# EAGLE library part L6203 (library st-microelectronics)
DMOS FULL BRIDGE DRIVER
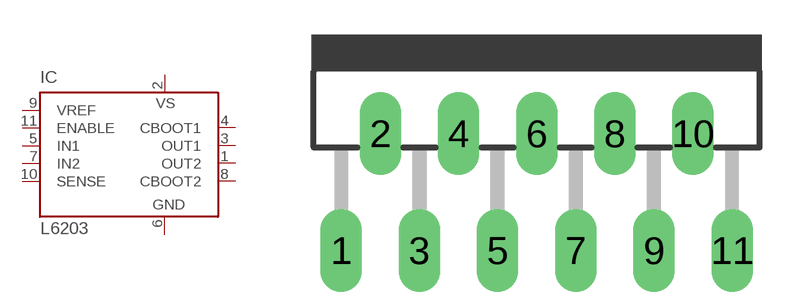
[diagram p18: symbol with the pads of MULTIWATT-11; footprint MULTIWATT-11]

Designator prefix IC

## L6203 (MPN: L6203; OC_FARNELL: 1467715; OC_NEWARK: 56P8434)  [MULTIWATT-11]
1  OUT2  out
2  VS  pwr
3  OUT1  out
4  CBOOT1  in
5  IN1  in
6  GND  pwr
7  IN2  in
8  CBOOT2  in
9  VREF  in
10  SENSE  in
11  ENABLE  in

## Footprint MULTIWATT-11 (pad centres in mm)
Muliwatt 11 lead
drill 1.2 long: 1 -8.5,-6.35; 2 -6.8,-1.27; 3 -5.1,-6.35; 4 -3.4,-1.27; 5 -1.7,-6.35; 6 0,-1.27; 7 1.7,-6.35; 8 3.4,-1.27; 9 5.1,-6.35; 10 6.8,-1.27; 11 8.5,-6.35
